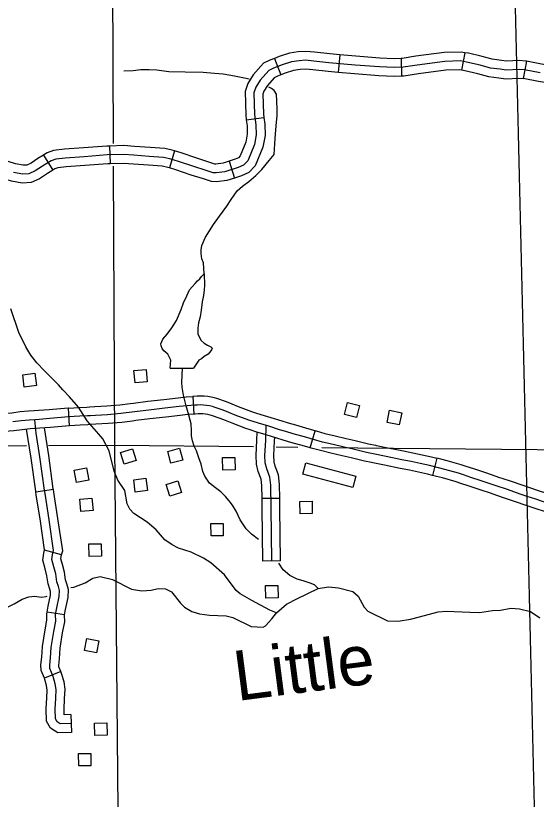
# Model space of a CAD drawing. Extents: x -19 to 366, y -4 to 359.
# Drawn here: x 134.232 to 135.065, y 193.481 to 194.735 of the extents above; entities that cross this region are included whole.
import ezdxf

# ---------------------------------------------------------------- set-up
doc = ezdxf.new("R2010")
doc.units = 0
for name, color, linetype in [('21', 7, 'Continuous'), ('R_Axis Annot', 7, 'Continuous'), ('R_ROW', 7, 'Continuous'), ('R_ROW Annot', 7, 'Continuous'), ('R_Temp Easement', 7, 'Continuous'), ('Sheet Fence', 7, 'Continuous')]:
    doc.layers.add(name, color=color, linetype=linetype)

msp = doc.modelspace()

# ---------------------------------------------------------------- linework, layer by layer
at = {"layer": '21'}
for points in [[(134.4209, 194.1673), (134.4406, 194.1691), (134.4424, 194.1494), (134.4228, 194.1476)], [(134.2429, 194.1606), (134.2625, 194.1631), (134.265, 194.1434), (134.2454, 194.1409)], [(134.7631, 194.1161), (134.7822, 194.1112), (134.7773, 194.092), (134.7582, 194.0969)], [(134.8304, 194.1037), (134.8497, 194.0996), (134.8456, 194.0803), (134.8263, 194.0843)], [(134.4244, 194.0232), (134.4055, 194.0174), (134.3997, 194.0363), (134.4186, 194.0421)], [(134.4993, 194.024), (134.4803, 194.0189), (134.4751, 194.0379), (134.4941, 194.0431)], [(134.5831, 194.0085), (134.5634, 194.0081), (134.563, 194.0279), (134.5827, 194.0283)], [(134.6912, 194.0013), (134.6961, 194.0196), (134.7761, 193.9982), (134.7712, 193.9799)], [(134.3254, 194.0078), (134.3448, 194.0114), (134.3485, 193.992), (134.3291, 193.9883)], [(134.4206, 193.9924), (134.4402, 193.9949), (134.4427, 193.9752), (134.4231, 193.9728)], [(134.4725, 193.9849), (134.4913, 193.9908), (134.4972, 193.972), (134.4784, 193.9661)], [(134.3342, 193.9612), (134.3538, 193.9632), (134.3558, 193.9435), (134.3362, 193.9415)], [(134.7066, 193.9385), (134.6869, 193.9381), (134.6865, 193.9578), (134.7062, 193.9582)], [(134.5641, 193.903), (134.5444, 193.9026), (134.544, 193.9223), (134.5637, 193.9227)], [(134.3691, 193.8703), (134.3494, 193.8699), (134.349, 193.8897), (134.3687, 193.8901)], [(134.6518, 193.8036), (134.6321, 193.8032), (134.6317, 193.823), (134.6514, 193.8234)], [(134.3456, 193.7386), (134.3649, 193.7345), (134.3609, 193.7152), (134.3416, 193.7192)], [(134.3779, 193.5836), (134.3582, 193.5832), (134.3578, 193.603), (134.3776, 193.6034)], [(134.3522, 193.5347), (134.3325, 193.5343), (134.3321, 193.5541), (134.3518, 193.5545)]]:
    msp.add_lwpolyline(points, close=True, dxfattribs=at)
at = {"layer": 'R_Axis Annot'}
for points in [[(134.3857, 195.0473), (134.3877, 194.5307)], [(134.3878, 194.4948), (134.3896, 194.0472)], [(134.2491, 194.0469), (133.84, 194.0459)], [(134.3896, 194.0472), (134.2841, 194.0469)], [(134.3896, 194.0472), (134.3989, 193.0554)], [(134.6123, 194.045), (134.3896, 194.0472)], [(134.6835, 194.0443), (134.6486, 194.0446)], [(135.124, 194.04), (134.7216, 194.0439)]]:
    msp.add_lwpolyline(points, dxfattribs=at)
at = {"layer": 'R_ROW'}
for p, q in [((134.5152, 194.1259), (134.5169, 194.0975)), ((134.3179, 194.0788), (134.3161, 194.1072)), ((134.7034, 194.0436), (134.7114, 194.0709)), ((134.8015, 194.02), (134.8015, 194.02)), ((134.9057, 194.027), (134.8991, 193.9994))]:
    msp.add_line(p, q, dxfattribs=at)
for points in [[(134.4149, 194.1147), (134.4203, 194.1154), (134.4431, 194.1182), (134.4686, 194.1211), (134.4917, 194.1237), (134.5047, 194.1252), (134.5152, 194.1259)], [(134.6159, 194.0993), (134.6097, 194.1014), (134.5884, 194.1093), (134.5784, 194.1134), (134.569, 194.1174), (134.5536, 194.1225), (134.5502, 194.1235), (134.5447, 194.1248), (134.5391, 194.1257), (134.5335, 194.1263), (134.5278, 194.1265), (134.5221, 194.1264), (134.517, 194.126), (134.5152, 194.1259)], [(134.3161, 194.1072), (134.3154, 194.1071), (134.2851, 194.1047), (134.2683, 194.1034), (134.2613, 194.1029), (134.2523, 194.1022), (134.239, 194.101), (134.2252, 194.0993), (134.2175, 194.0984), (134.2156, 194.0981)], [(135.0877, 193.9536), (135.0645, 193.9613), (135.0505, 193.9659), (135.0396, 193.9697), (135.0191, 193.9767), (134.9992, 193.9834), (134.9784, 193.9904), (134.9751, 193.9915), (134.9606, 193.9964), (134.9487, 194.0003), (134.9408, 194.0029), (134.9186, 194.0092), (134.9087, 194.0117), (134.8942, 194.0152), (134.8795, 194.0185), (134.8649, 194.0216), (134.8499, 194.0246), (134.8249, 194.0296), (134.8066, 194.0334), (134.7932, 194.0363), (134.7718, 194.0414), (134.7577, 194.0446), (134.7398, 194.0488), (134.7231, 194.0529), (134.7086, 194.0569), (134.6979, 194.06), (134.6761, 194.066), (134.6642, 194.0697), (134.6539, 194.0727), (134.6367, 194.0781), (134.6206, 194.0829), (134.605, 194.0879), (134.5832, 194.0961), (134.5729, 194.1003), (134.564, 194.1041), (134.5494, 194.1089), (134.5466, 194.1097), (134.5419, 194.1108), (134.5372, 194.1116), (134.5324, 194.1121), (134.5276, 194.1123), (134.5229, 194.1122), (134.5181, 194.1118), (134.506, 194.1111), (134.4934, 194.1096), (134.4702, 194.107), (134.4447, 194.1041), (134.422, 194.1013), (134.4, 194.0985), (134.3785, 194.0966), (134.3593, 194.0955), (134.3513, 194.095), (134.3464, 194.0948), (134.3342, 194.0941), (134.3164, 194.093), (134.2862, 194.0905), (134.2693, 194.0892), (134.2623, 194.0887)], [(134.3161, 194.1072), (134.3334, 194.1083), (134.3457, 194.109), (134.3506, 194.1092), (134.3585, 194.1096), (134.3775, 194.1107), (134.3984, 194.1126), (134.4149, 194.1147)], [(134.5169, 194.0975), (134.5073, 194.0969), (134.495, 194.0955), (134.4718, 194.0929), (134.4464, 194.09), (134.4238, 194.0872), (134.4185, 194.0865)], [(134.6071, 194.0723), (134.6003, 194.0745), (134.578, 194.0829), (134.5674, 194.0872), (134.559, 194.0908), (134.5453, 194.0953), (134.543, 194.096), (134.5391, 194.0969), (134.5353, 194.0975), (134.5314, 194.0979), (134.5275, 194.0981), (134.5236, 194.098), (134.5191, 194.0976), (134.5169, 194.0975)], [(134.7114, 194.0709), (134.7018, 194.0737), (134.6801, 194.0797), (134.6683, 194.0833), (134.6581, 194.0863), (134.6409, 194.0917), (134.6248, 194.0964), (134.6159, 194.0993)], [(134.2623, 194.0887), (134.2534, 194.0881), (134.2405, 194.0869), (134.227, 194.0852)], [(134.4185, 194.0865), (134.4015, 194.0844), (134.3795, 194.0824), (134.3602, 194.0813), (134.352, 194.0808), (134.347, 194.0806), (134.3351, 194.0799), (134.3179, 194.0788)], [(134.318, 194.0788), (134.3174, 194.0788), (134.2873, 194.0763), (134.2703, 194.075), (134.2633, 194.0745), (134.2546, 194.0739), (134.242, 194.0727), (134.2287, 194.0711), (134.2211, 194.0702), (134.2193, 194.07)], [(134.7034, 194.0436), (134.694, 194.0464), (134.6722, 194.0524), (134.6601, 194.0561), (134.6498, 194.0591), (134.6326, 194.0645), (134.6163, 194.0693), (134.6071, 194.0723)], [(134.7114, 194.0709), (134.7125, 194.0706), (134.7267, 194.0667), (134.7431, 194.0626), (134.7609, 194.0584), (134.775, 194.0553), (134.7964, 194.0502), (134.8076, 194.0477)], [(134.8015, 194.02), (134.79, 194.0225), (134.7686, 194.0276), (134.7545, 194.0307), (134.7365, 194.035), (134.7196, 194.0392), (134.7048, 194.0432), (134.7034, 194.0436)], [(134.8076, 194.0477), (134.8095, 194.0473), (134.8277, 194.0436), (134.8527, 194.0386), (134.8677, 194.0355), (134.8826, 194.0324), (134.8974, 194.029), (134.9057, 194.027)], [(134.8991, 193.9994), (134.8909, 194.0014), (134.8765, 194.0046), (134.862, 194.0077), (134.8471, 194.0107), (134.8221, 194.0157), (134.8036, 194.0195), (134.8015, 194.02)], [(135.0025, 193.9973), (134.9829, 194.0039), (134.9796, 194.005), (134.9651, 194.0099), (134.9531, 194.0138), (134.9449, 194.0165), (134.9223, 194.0229), (134.9122, 194.0255), (134.9057, 194.027)], [(134.9934, 193.9704), (134.9739, 193.9769), (134.9706, 193.9781), (134.9561, 193.9829), (134.9442, 193.9868), (134.9367, 193.9893), (134.9149, 193.9954), (134.9053, 193.9979), (134.8991, 193.9994)], [(135.0972, 193.9654), (135.0922, 193.9671), (135.0689, 193.9747), (135.055, 193.9794), (135.0442, 193.9831), (135.0237, 193.9901), (135.0038, 193.9969), (135.0025, 193.9973)], [(135.0882, 193.9385), (135.0833, 193.9401), (135.06, 193.9478), (135.0459, 193.9525), (135.035, 193.9562), (135.0145, 193.9632), (134.9946, 193.97), (134.9934, 193.9704)]]:
    msp.add_lwpolyline(points, dxfattribs=at)
at = {"layer": 'R_ROW Annot'}
for p, q in [((134.7505, 194.6728), (134.748, 194.6445)), ((134.9509, 194.6762), (134.9457, 194.6483)), ((134.6459, 194.6671), (134.6561, 194.6406)), ((134.8486, 194.667), (134.8495, 194.6386)), ((135.0493, 194.6626), (135.0441, 194.6347)), ((134.6009, 194.569), (134.6291, 194.5726)), ((134.3819, 194.5268), (134.3827, 194.4984)), ((134.2764, 194.5124), (134.2913, 194.4882)), ((134.4858, 194.519), (134.4777, 194.4918)), ((134.5734, 194.5024), (134.5821, 194.4754)), ((134.2921, 193.977), (134.264, 193.9728)), ((134.6546, 193.9627), (134.6262, 193.9624)), ((134.3052, 193.8724), (134.2779, 193.8799)), ((134.6557, 193.8627), (134.6273, 193.8624)), ((134.3098, 193.7761), (134.2818, 193.7808)), ((134.3038, 193.6854), (134.2775, 193.6747)), ((134.32, 193.6165), (134.3208, 193.5881))]:
    msp.add_line(p, q, dxfattribs=at)
for points in [[(134.7505, 194.6728), (134.7346, 194.6742), (134.7102, 194.6768), (134.696, 194.6782), (134.6841, 194.6774), (134.6703, 194.6755), (134.6535, 194.67), (134.6459, 194.6671)], [(134.8486, 194.667), (134.8378, 194.6666), (134.8148, 194.6676), (134.7764, 194.6705), (134.7505, 194.6728)], [(134.9509, 194.6762), (134.945, 194.6773), (134.9179, 194.6765), (134.8723, 194.6705), (134.8505, 194.667), (134.8486, 194.667)], [(135.0493, 194.6626), (135.0481, 194.6628), (135.0377, 194.6635), (135.0177, 194.6625), (135.0094, 194.6637), (134.9948, 194.6656), (134.9788, 194.6699), (134.9565, 194.6752), (134.9509, 194.6762)], [(135.0714, 194.644), (135.0463, 194.6487), (135.0376, 194.6493), (135.017, 194.6482), (135.0075, 194.6496), (134.992, 194.6516), (134.9753, 194.6561), (134.9535, 194.6613), (134.9439, 194.6631), (134.919, 194.6623), (134.8743, 194.6564), (134.8518, 194.6529), (134.8377, 194.6524), (134.814, 194.6534), (134.7752, 194.6564), (134.7332, 194.6601), (134.7088, 194.6627), (134.6958, 194.664), (134.6855, 194.6632), (134.6735, 194.6616), (134.6583, 194.6566), (134.6444, 194.6513), (134.637, 194.6477), (134.6233, 194.6323), (134.6162, 194.6209), (134.6131, 194.6121), (134.6142, 194.5774), (134.6163, 194.5605), (134.6168, 194.5447), (134.6139, 194.5292), (134.6031, 194.5031), (134.5966, 194.4962), (134.588, 194.4922), (134.5667, 194.4854), (134.5526, 194.4837), (134.548, 194.484), (134.5364, 194.4877), (134.5171, 194.4938), (134.4924, 194.5022), (134.4785, 194.5063), (134.4685, 194.5085), (134.4456, 194.5103), (134.421, 194.5121), (134.4044, 194.5133), (134.3783, 194.5125), (134.3412, 194.5096), (134.311, 194.5075), (134.2957, 194.5058), (134.2883, 194.503), (134.2748, 194.4947), (134.263, 194.4869), (134.2528, 194.4824), (134.2428, 194.4817), (134.2282, 194.4846)], [(134.6459, 194.6671), (134.6387, 194.6643), (134.6283, 194.6593), (134.6119, 194.6409), (134.6033, 194.627), (134.5989, 194.6142), (134.6, 194.5763), (134.6009, 194.569)], [(135.1411, 194.6527), (135.1334, 194.6504), (135.1278, 194.6497), (135.1102, 194.6521), (135.0738, 194.658), (135.0493, 194.6626)], [(134.748, 194.6445), (134.7318, 194.646), (134.7073, 194.6486), (134.6956, 194.6497), (134.6869, 194.6491), (134.6767, 194.6477), (134.663, 194.6432), (134.6561, 194.6406)], [(134.9457, 194.6483), (134.9428, 194.6488), (134.9202, 194.6482), (134.8764, 194.6424), (134.8531, 194.6387), (134.8495, 194.6386)], [(135.0445, 194.6346), (135.0374, 194.635), (135.0164, 194.634), (135.0055, 194.6355), (134.9893, 194.6377), (134.9718, 194.6424), (134.9506, 194.6474), (134.9457, 194.6483)], [(134.6561, 194.6406), (134.65, 194.6382), (134.6457, 194.6362), (134.6347, 194.6238), (134.6291, 194.6147), (134.6274, 194.6099), (134.6283, 194.5786), (134.6291, 194.5726)], [(134.8495, 194.6386), (134.8376, 194.6382), (134.8131, 194.6392), (134.7741, 194.6422), (134.748, 194.6445)], [(135.1492, 194.6254), (135.1393, 194.6225), (135.1276, 194.621), (135.106, 194.624), (135.0689, 194.6301), (135.0441, 194.6347)], [(134.6291, 194.5726), (134.6305, 194.5616), (134.631, 194.5436), (134.6276, 194.5251), (134.6152, 194.4952), (134.6051, 194.4845), (134.5932, 194.479), (134.5821, 194.4754)], [(134.6009, 194.569), (134.6021, 194.5593), (134.6025, 194.5458), (134.6002, 194.5332), (134.591, 194.5109), (134.5882, 194.508), (134.5829, 194.5055), (134.5734, 194.5024)], [(134.3819, 194.5268), (134.3775, 194.5267), (134.3402, 194.5238), (134.3097, 194.5216), (134.2924, 194.5197), (134.282, 194.5159), (134.2764, 194.5124)], [(134.4858, 194.519), (134.4821, 194.5201), (134.4706, 194.5226), (134.4467, 194.5245), (134.4221, 194.5263), (134.4047, 194.5275), (134.3819, 194.5268)], [(134.2764, 194.5124), (134.2672, 194.5067), (134.2562, 194.4994), (134.2493, 194.4964), (134.2437, 194.496), (134.2315, 194.4984), (134.2194, 194.5019), (134.206, 194.5064), (134.1926, 194.5085)], [(134.5734, 194.5024), (134.5636, 194.4993), (134.5522, 194.4979), (134.5507, 194.498), (134.5407, 194.5012), (134.5216, 194.5073), (134.4967, 194.5157), (134.4858, 194.519)], [(134.3827, 194.4984), (134.379, 194.4983), (134.3423, 194.4955), (134.3123, 194.4933), (134.299, 194.4918), (134.2945, 194.4902), (134.2913, 194.4882)], [(134.4777, 194.4918), (134.475, 194.4926), (134.4664, 194.4944), (134.4445, 194.4962), (134.42, 194.4979), (134.4041, 194.499), (134.3827, 194.4984)], [(134.2913, 194.4882), (134.2825, 194.4828), (134.2698, 194.4744), (134.2562, 194.4684), (134.2419, 194.4674), (134.2248, 194.4708), (134.211, 194.4748), (134.1992, 194.4787), (134.1882, 194.4805)], [(134.5821, 194.4754), (134.5697, 194.4714), (134.553, 194.4694), (134.5454, 194.4699), (134.5321, 194.4742), (134.5127, 194.4803), (134.488, 194.4886), (134.4777, 194.4918)], [(134.3204, 193.6023), (134.3029, 193.6018), (134.298, 193.6048), (134.2952, 193.61), (134.2948, 193.6254), (134.2958, 193.6427), (134.2965, 193.6565), (134.2951, 193.666), (134.2916, 193.6776), (134.2865, 193.6902), (134.2863, 193.6955), (134.2875, 193.7072), (134.2886, 193.7242), (134.2926, 193.7498), (134.2958, 193.7664), (134.2955, 193.777), (134.2973, 193.7876), (134.3015, 193.8058), (134.3018, 193.8153), (134.3, 193.8217), (134.2976, 193.829), (134.2957, 193.8417), (134.2927, 193.8533), (134.2897, 193.8649), (134.2905, 193.8724), (134.2924, 193.8793), (134.2851, 193.9285), (134.2787, 193.9706), (134.2779, 193.976), (134.2704, 194.0294), (134.2645, 194.0669), (134.2623, 194.0887)], [(134.264, 193.9728), (134.2638, 193.974), (134.2564, 194.0273), (134.2491, 194.0736)], [(134.2921, 193.977), (134.2919, 193.978), (134.2845, 194.0315), (134.2776, 194.0755)], [(134.6262, 193.9624), (134.6259, 193.9831), (134.6248, 193.9933), (134.62, 194.0056), (134.617, 194.0174), (134.6165, 194.0314), (134.6179, 194.0559), (134.6183, 194.0687)], [(134.6415, 193.8626), (134.6406, 193.9471), (134.6401, 193.984), (134.6387, 193.9967), (134.6335, 194.01), (134.6312, 194.0194), (134.6307, 194.0312), (134.6321, 194.0553), (134.6328, 194.0792)], [(134.6546, 193.9627), (134.6543, 193.9849), (134.6526, 194.0002), (134.6471, 194.0143), (134.6453, 194.0214), (134.6449, 194.0311), (134.6463, 194.0547), (134.6464, 194.0602)], [(134.2779, 193.8799), (134.2779, 193.8802), (134.2711, 193.9264), (134.2646, 193.9685), (134.264, 193.9728)], [(134.3052, 193.8724), (134.3069, 193.8785), (134.2992, 193.9306), (134.2927, 193.9728), (134.2921, 193.977)], [(134.6273, 193.8624), (134.6264, 193.947), (134.6262, 193.9624)], [(134.6557, 193.8627), (134.6548, 193.9473), (134.6546, 193.9627)], [(134.2818, 193.7808), (134.2834, 193.7904), (134.2874, 193.8076), (134.2875, 193.8136), (134.2864, 193.8176), (134.2838, 193.8257), (134.2817, 193.8388), (134.2789, 193.8497), (134.2753, 193.8639), (134.2765, 193.8751), (134.2779, 193.8799)], [(134.3098, 193.7761), (134.3112, 193.7848), (134.3157, 193.804), (134.316, 193.8171), (134.3136, 193.8258), (134.3115, 193.8323), (134.3096, 193.8446), (134.3064, 193.8568), (134.3041, 193.866), (134.3045, 193.8697), (134.3052, 193.8724)], [(134.2775, 193.6747), (134.2723, 193.6872), (134.2721, 193.696), (134.2734, 193.7084), (134.2745, 193.7258), (134.2786, 193.7523), (134.2816, 193.7675), (134.2813, 193.7779), (134.2818, 193.7808)], [(134.3038, 193.6854), (134.3006, 193.6932), (134.3005, 193.695), (134.3017, 193.706), (134.3027, 193.7227), (134.3066, 193.7474), (134.3101, 193.7652), (134.3097, 193.776), (134.3098, 193.7761)], [(134.32, 193.6165), (134.3093, 193.6162), (134.309, 193.6252), (134.31, 193.642), (134.3107, 193.6572), (134.309, 193.6691), (134.305, 193.6824), (134.3038, 193.6854)], [(134.3208, 193.5881), (134.299, 193.5875), (134.2873, 193.5948), (134.2811, 193.6063), (134.2806, 193.6256), (134.2816, 193.6435), (134.2822, 193.6559), (134.2812, 193.663), (134.2782, 193.6728), (134.2775, 193.6747)]]:
    msp.add_lwpolyline(points, dxfattribs=at)
at = {"layer": 'R_Temp Easement'}
for points in [[(134.6053, 194.6337), (134.5979, 194.6354), (134.582, 194.6385), (134.564, 194.6417), (134.5498, 194.6429), (134.5319, 194.6447), (134.503, 194.6452), (134.4767, 194.6457), (134.4574, 194.6481), (134.4455, 194.649), (134.4319, 194.6487), (134.4196, 194.6473), (134.4047, 194.6464)], [(134.6454, 194.5133), (134.6467, 194.5304), (134.6476, 194.5464), (134.6491, 194.565), (134.6503, 194.5753), (134.6505, 194.5857), (134.6496, 194.5988), (134.6492, 194.6098), (134.6456, 194.6157), (134.641, 194.6191), (134.637, 194.6212)], [(134.5864, 194.4552), (134.5947, 194.4623), (134.6047, 194.4698), (134.6164, 194.4795), (134.6258, 194.4894), (134.6377, 194.5035), (134.6454, 194.5133)], [(134.5333, 194.322), (134.5323, 194.34), (134.5299, 194.3464), (134.5288, 194.3545), (134.5285, 194.3604), (134.5298, 194.3676), (134.5357, 194.3809), (134.5483, 194.4014), (134.5582, 194.4147), (134.5698, 194.4305), (134.5767, 194.4413), (134.5864, 194.4552)], [(134.4789, 194.171), (134.4803, 194.1839), (134.4779, 194.1884), (134.475, 194.1936), (134.4686, 194.199), (134.4661, 194.2024), (134.4645, 194.2069), (134.4642, 194.2099), (134.4654, 194.2137), (134.4672, 194.2176), (134.4742, 194.2255), (134.4816, 194.2355), (134.4892, 194.2473), (134.4968, 194.2649), (134.5005, 194.2756), (134.5054, 194.2872), (134.5099, 194.2968), (134.5141, 194.3015), (134.5189, 194.3069), (134.5226, 194.311), (134.5265, 194.3143), (134.5289, 194.3177), (134.5333, 194.322), (134.5337, 194.3042), (134.5333, 194.2964), (134.5326, 194.2877), (134.5303, 194.2776), (134.5287, 194.2639), (134.5269, 194.2534), (134.5243, 194.2439), (134.5235, 194.2351), (134.5235, 194.2264), (134.5252, 194.2213), (134.5287, 194.2155), (134.5333, 194.2111), (134.5385, 194.208), (134.5439, 194.2054), (134.546, 194.2034), (134.5453, 194.2003), (134.544, 194.1988), (134.5396, 194.1934), (134.5336, 194.1896), (134.5292, 194.1863), (134.5249, 194.1839), (134.5161, 194.1714)], [(134.6494, 193.7797), (134.6384, 193.7837), (134.6099, 193.799), (134.5909, 193.8098), (134.5844, 193.8154), (134.566, 193.8403), (134.5439, 193.8597), (134.5325, 193.8668), (134.5127, 193.8765), (134.4923, 193.8831), (134.482, 193.8883), (134.4706, 193.8962), (134.4568, 193.9123), (134.4423, 193.9247), (134.421, 193.9385), (134.4142, 193.9453), (134.4103, 193.954), (134.4063, 193.9755), (134.3952, 193.9917), (134.3894, 194.0061), (134.3812, 194.0386), (134.3712, 194.0578), (134.365, 194.0657), (134.3459, 194.0871), (134.3321, 194.109), (134.318, 194.1255), (134.3069, 194.1364), (134.3004, 194.1447), (134.2775, 194.1668), (134.2657, 194.1796), (134.2561, 194.192), (134.2477, 194.2052), (134.2365, 194.2282), (134.224, 194.266)], [(134.4789, 194.171), (134.4985, 194.1714), (134.5161, 194.1714)], [(134.6206, 193.8967), (134.6204, 193.8969), (134.6094, 193.9052), (134.6009, 193.9137), (134.5913, 193.9286), (134.5846, 193.9425), (134.579, 193.9521), (134.5734, 193.9588), (134.5678, 193.9655), (134.5599, 193.9733), (134.5518, 193.9797), (134.5422, 193.9873), (134.5347, 193.9983), (134.5313, 194.0058), (134.5284, 194.0175), (134.525, 194.0275), (134.521, 194.0386), (134.5174, 194.0465), (134.5147, 194.0546), (134.5134, 194.0627), (134.5134, 194.0712), (134.5124, 194.0818), (134.5112, 194.0879), (134.5091, 194.0958), (134.5048, 194.1107), (134.5002, 194.128), (134.4984, 194.1407), (134.4975, 194.1483), (134.4985, 194.1714)], [(134.7159, 193.8182), (134.7101, 193.8243), (134.7034, 193.8268), (134.6918, 193.8306), (134.6824, 193.8336), (134.6708, 193.8392), (134.66, 193.8484), (134.6529, 193.8592)], [(134.3199, 193.8202), (134.3246, 193.8208), (134.3431, 193.8275), (134.3551, 193.8352), (134.3668, 193.8375), (134.3865, 193.8328), (134.4169, 193.8176), (134.4336, 193.8147), (134.4487, 193.8156), (134.4596, 193.8184), (134.4713, 193.8177), (134.4812, 193.8129), (134.4954, 193.7952), (134.5018, 193.7888), (134.5136, 193.7814), (134.5261, 193.7777), (134.542, 193.7756), (134.5685, 193.7747), (134.5791, 193.7718), (134.6087, 193.7577), (134.628, 193.7567), (134.6314, 193.7586), (134.6419, 193.7697), (134.6494, 193.7797), (134.6655, 193.7931), (134.6817, 193.802), (134.7159, 193.8182), (134.7325, 193.821), (134.7484, 193.8193), (134.7712, 193.8138), (134.7799, 193.8063), (134.7895, 193.7886), (134.7956, 193.7819), (134.8272, 193.7666), (134.8438, 193.766), (134.8638, 193.7693), (134.8781, 193.7732), (134.9083, 193.7811), (134.9212, 193.7823), (134.9586, 193.7804), (134.9741, 193.7798), (134.9949, 193.7831), (135.0077, 193.7839), (135.0243, 193.7868), (135.0383, 193.7861), (135.0561, 193.7814)], [(134.021, 193.7053), (134.0505, 193.7082), (134.0705, 193.708), (134.0993, 193.7053), (134.1144, 193.7062), (134.1249, 193.7105), (134.1366, 193.7193), (134.1699, 193.7499), (134.18, 193.7622), (134.1987, 193.779), (134.2292, 193.7937), (134.242, 193.8011), (134.2526, 193.8053), (134.2624, 193.8062), (134.2726, 193.8048), (134.2802, 193.8056), (134.2819, 193.8061)], [(135.0561, 193.7814), (135.071, 193.7714)]]:
    msp.add_lwpolyline(points, dxfattribs=at)
at = {"layer": 'Sheet Fence'}
for points in [[(139.4406, 1.5315), (139.2511, 10.1473), (139.0608, 18.7633), (138.8699, 27.3793), (138.6784, 35.9956), (138.4861, 44.6119), (138.2932, 53.2285), (138.0997, 61.8451), (137.9055, 70.4619), (137.7106, 79.0789), (137.5151, 87.6959), (137.319, 96.3132), (137.1221, 104.9306), (136.9247, 113.5481), (136.7265, 122.1658), (136.5278, 130.7836), (136.3283, 139.4016), (136.1282, 148.0197), (135.9275, 156.6379), (135.7261, 165.2564), (135.5241, 173.8749), (135.3214, 182.4936), (135.1181, 191.1125), (134.9141, 199.7315), (134.7095, 208.3506), (134.5043, 216.9699), (134.2984, 225.5894), (134.0919, 234.209), (133.8847, 242.8288), (133.6769, 251.4487), (133.4685, 260.0687), (133.2594, 268.6889), (133.0497, 277.3093), (132.8393, 285.9298), (132.6283, 294.5504), (132.4167, 303.1713), (132.2044, 311.7922), (131.9916, 320.4133), (131.778, 329.0346), (131.5639, 337.656), (131.3491, 346.2776)], [(0, 189.5162), (7.1121, 189.5206), (14.2243, 189.5339), (21.3364, 189.556), (28.4484, 189.5869), (35.5605, 189.6267), (42.6725, 189.6754), (49.7844, 189.7329), (56.8962, 189.7992), (64.0079, 189.8744), (71.1196, 189.9584), (78.2311, 190.0512), (85.3425, 190.1529), (92.4538, 190.2635), (99.5649, 190.3829), (106.6759, 190.5111), (113.7867, 190.6482), (120.8974, 190.7941), (128.0078, 190.9489), (135.1181, 191.1125), (142.2282, 191.2849), (149.338, 191.4662), (156.4476, 191.6563), (163.5569, 191.8553), (170.666, 192.0631), (177.7749, 192.2798), (184.8835, 192.5053), (191.9917, 192.7396), (199.0997, 192.9828), (206.2074, 193.2348), (213.3147, 193.4956), (220.4218, 193.7653), (227.5285, 194.0438), (234.6348, 194.3312), (241.7408, 194.6274), (248.8464, 194.9324), (255.9516, 195.2463), (263.0564, 195.569), (270.1608, 195.9005), (277.2648, 196.2409), (284.3683, 196.5901), (291.4715, 196.9481), (298.5741, 197.315), (305.6763, 197.6907), (312.7781, 198.0753), (319.8793, 198.4686), (326.9801, 198.8708), (334.0804, 199.2818), (341.1801, 199.7017)]]:
    msp.add_spline(points, degree=3, dxfattribs=at)

# ---------------------------------------------------------------- texts
at = {"layer": 'R_Temp Easement'}
msp.add_text('Little', height=0.08, rotation=7.3869, dxfattribs=at).set_placement((134.5861, 193.6382))

doc.saveas('drawing.dxf')
